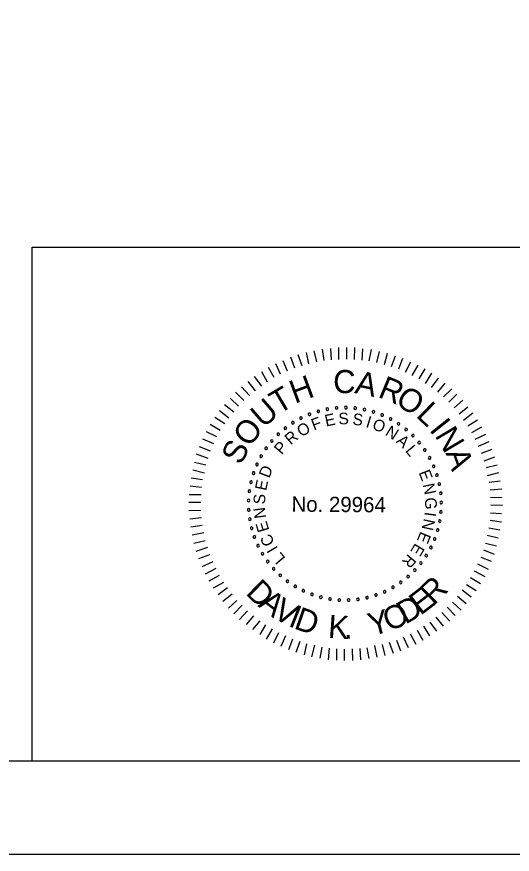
# Model space of a CAD drawing. Extents: x -144.4 to -96.3, y -117.1 to -87.8.
# Drawn here: x -114.36 to -110.83, y -117.06 to -111.1 of the extents above; entities that cross this region are included whole.
import ezdxf

# ---------------------------------------------------------------- set-up
doc = ezdxf.new("R2010")
doc.units = 0
for name, color, linetype in [('BR_BORDER LINES', 7, 'Continuous'), ('BR_TEXT', 7, 'Continuous'), ('Level 31', 7, 'Continuous')]:
    doc.layers.add(name, color=color, linetype=linetype)

msp = doc.modelspace()

# ---------------------------------------------------------------- linework, layer by layer
at = {"layer": 'BR_BORDER LINES'}
for p, q in [((-114.2473, -112.7399), (-107.1116, -112.7399)), ((-114.2473, -116.3975), (-114.2473, -112.7399)), ((-141.9121, -116.3976), (-97.1362, -116.3976))]:
    msp.add_line(p, q, dxfattribs=at)
at = {"layer": 'BR_TEXT'}
for p, q in [((-112.2228, -113.557), (-112.2416, -113.4781)), ((-112.1703, -113.5472), (-112.1822, -113.4661)), ((-112.1177, -113.5419), (-112.1228, -113.4608)), ((-112.0652, -113.5389), (-112.0645, -113.4533)), ((-112.0093, -113.536), (-112.0086, -113.4538)), ((-111.9533, -113.5398), (-111.9504, -113.4542)), ((-111.8998, -113.5437), (-111.8934, -113.4627)), ((-111.8484, -113.5498), (-111.834, -113.4689)), ((-111.7949, -113.5606), (-111.776, -113.4819)), ((-112.3785, -113.6003), (-112.4063, -113.5224)), ((-112.3258, -113.5835), (-112.3549, -113.5069)), ((-112.2778, -113.5703), (-112.2953, -113.4891)), ((-111.7402, -113.5747), (-111.719, -113.4939)), ((-111.6913, -113.5888), (-111.6621, -113.5126)), ((-111.6389, -113.6064), (-111.6097, -113.529)), ((-112.5251, -113.6687), (-112.5656, -113.5964)), ((-112.4793, -113.6451), (-112.5141, -113.5706)), ((-112.43, -113.6227), (-112.4613, -113.5482)), ((-111.5911, -113.6296), (-111.554, -113.5557)), ((-111.5434, -113.6528), (-111.5017, -113.579)), ((-111.4934, -113.6772), (-111.4505, -113.6056)), ((-112.6135, -113.7284), (-112.6654, -113.6607)), ((-112.5722, -113.7002), (-112.6126, -113.628)), ((-111.4491, -113.7095), (-111.404, -113.6379)), ((-112.6583, -113.7623), (-112.7114, -113.6956)), ((-111.4048, -113.7384), (-111.3563, -113.6715)), ((-111.3618, -113.773), (-111.3076, -113.7072)), ((-112.741, -113.8312), (-112.7999, -113.7725)), ((-112.702, -113.795), (-112.7574, -113.7352)), ((-111.3198, -113.8064), (-111.2623, -113.7476)), ((-111.2825, -113.8433), (-111.2249, -113.7855)), ((-112.7802, -113.872), (-112.838, -113.8156)), ((-111.2451, -113.8847), (-111.1819, -113.8293)), ((-112.8482, -113.9582), (-112.914, -113.9051)), ((-112.8136, -113.914), (-112.8794, -113.862)), ((-111.209, -113.9272), (-111.1469, -113.8764)), ((-112.8771, -113.9967), (-112.9486, -113.9528)), ((-111.1773, -113.972), (-111.1119, -113.92)), ((-112.9095, -114.0456), (-112.981, -114.0028)), ((-111.148, -114.011), (-111.0781, -113.9682)), ((-111.1187, -114.0604), (-111.0476, -114.0187)), ((-112.9327, -114.091), (-113.0077, -114.0539)), ((-111.0952, -114.1062), (-111.0184, -114.0703)), ((-112.9559, -114.1399), (-113.0321, -114.1062)), ((-111.0716, -114.1555), (-110.996, -114.123)), ((-112.9792, -114.1911), (-113.0565, -114.1619)), ((-111.0492, -114.2071), (-110.9736, -114.1791)), ((-112.9956, -114.2446), (-113.0775, -114.2143)), ((-111.0314, -114.2608), (-110.9546, -114.2318)), ((-113.0119, -114.2924), (-113.0928, -114.2723)), ((-111.018, -114.3089), (-110.938, -114.2901)), ((-113.0215, -114.3483), (-113.1047, -114.327)), ((-111.0071, -114.3649), (-110.927, -114.345)), ((-113.0418, -114.4508), (-113.1239, -114.441)), ((-113.0356, -114.3961), (-113.1166, -114.3851)), ((-110.9961, -114.4129), (-110.9173, -114.4033)), ((-110.9874, -114.4678), (-110.9063, -114.4593)), ((-113.0484, -114.558), (-113.1317, -114.5573)), ((-113.0456, -114.5033), (-113.1312, -114.5026)), ((-110.9856, -114.5203), (-110.9057, -114.521)), ((-113.0466, -114.6151), (-113.1322, -114.6167)), ((-110.9826, -114.5751), (-110.9016, -114.5757)), ((-113.0436, -114.6665), (-113.1258, -114.6761)), ((-110.9865, -114.6321), (-110.9066, -114.6351)), ((-113.0383, -114.7213), (-113.1195, -114.7332)), ((-110.9988, -114.7382), (-110.9201, -114.7514)), ((-110.9892, -114.6835), (-110.9082, -114.6944)), ((-113.0251, -114.774), (-113.1085, -114.7915)), ((-111.0106, -114.7906), (-110.9309, -114.8095)), ((-113.0164, -114.83), (-113.0976, -114.8487)), ((-111.0225, -114.8464), (-110.9428, -114.8665)), ((-113.0008, -114.8791), (-113.0832, -114.907)), ((-111.0366, -114.8954), (-110.9604, -114.9245)), ((-112.9853, -114.9306), (-113.0631, -114.9585)), ((-111.0553, -114.9466), (-110.9802, -114.9757)), ((-112.9628, -114.9799), (-113.0396, -115.0158)), ((-112.9404, -115.028), (-113.016, -115.0674)), ((-111.0785, -114.9955), (-111.0035, -115.0326)), ((-112.918, -115.0773), (-112.9902, -115.1189)), ((-111.1273, -115.0921), (-111.0568, -115.1349)), ((-111.1029, -115.0432), (-111.0267, -115.0838)), ((-112.8864, -115.1267), (-112.9587, -115.1683)), ((-111.1574, -115.1409), (-111.0881, -115.1837)), ((-112.8582, -115.1657), (-112.9248, -115.2142)), ((-112.8244, -115.2105), (-112.891, -115.2624)), ((-111.1873, -115.1795), (-111.1227, -115.2291)), ((-112.7916, -115.2553), (-112.8503, -115.3096)), ((-111.2565, -115.2679), (-111.1942, -115.3233)), ((-111.2197, -115.2237), (-111.1585, -115.2768)), ((-112.7531, -115.2898), (-112.8129, -115.3498)), ((-112.7146, -115.3301), (-112.771, -115.3913)), ((-111.2945, -115.3019), (-111.2379, -115.3628)), ((-112.6715, -115.3647), (-112.7257, -115.427)), ((-111.375, -115.3754), (-111.3219, -115.4386)), ((-111.3325, -115.3415), (-111.276, -115.4036)), ((-112.6273, -115.3993), (-112.6803, -115.4628)), ((-112.5864, -115.4282), (-112.6281, -115.4974)), ((-111.4634, -115.4375), (-111.4194, -115.5074)), ((-111.4186, -115.4093), (-111.3712, -115.4736)), ((-112.5399, -115.4582), (-112.5816, -115.5298)), ((-112.4944, -115.4848), (-112.5305, -115.5588)), ((-112.4456, -115.5081), (-112.4781, -115.582)), ((-111.6067, -115.515), (-111.5708, -115.5895)), ((-111.5586, -115.4926), (-111.5181, -115.5671)), ((-111.5081, -115.4667), (-111.4665, -115.539)), ((-112.3944, -115.5313), (-112.4235, -115.6064)), ((-112.342, -115.5477), (-112.3724, -115.6251)), ((-112.2942, -115.5641), (-112.3131, -115.6427)), ((-112.2395, -115.5737), (-112.2596, -115.6557)), ((-111.7567, -115.5686), (-111.7368, -115.6475)), ((-111.7075, -115.553), (-111.6796, -115.6308)), ((-111.6548, -115.5374), (-111.6269, -115.613)), ((-112.1872, -115.589), (-112.2003, -115.6665)), ((-112.1347, -115.5951), (-112.1411, -115.6773)), ((-112.0822, -115.599), (-112.0829, -115.6812)), ((-112.0263, -115.6029), (-112.027, -115.6839)), ((-111.9704, -115.5999), (-111.9688, -115.6821)), ((-111.9167, -115.5969), (-111.9117, -115.6791)), ((-111.8653, -115.5917), (-111.8522, -115.6693)), ((-111.8115, -115.5772), (-111.794, -115.6596))]:
    msp.add_line(p, q, dxfattribs=at)
for centre, start, end in [((-112.2114, -113.9083), 16.14222, 196.14222), ((-112.1469, -113.8931), 10.60376, 190.60376), ((-112.1469, -113.8931), 190.60376, 10.60376), ((-112.0812, -113.8842), 5.06529, 185.06529), ((-112.0812, -113.8842), 185.06529, 5.06529), ((-112.015, -113.8817), 359.52683, 179.52683), ((-112.015, -113.8817), 179.52683, 359.52683), ((-111.9488, -113.8855), 353.98837, 173.98837), ((-111.9488, -113.8855), 173.98837, 353.98837), ((-111.8833, -113.8958), 168.44991, 348.44991), ((-111.8833, -113.8958), 348.44991, 168.44991), ((-111.8191, -113.9123), 342.91145, 162.91145), ((-112.3345, -113.957), 27.21914, 207.21914), ((-112.3345, -113.957), 207.21914, 27.21914), ((-112.2741, -113.9297), 21.68068, 201.68068), ((-112.2741, -113.9297), 201.68068, 21.68068), ((-112.2114, -113.9083), 196.14222, 16.14222), ((-111.8191, -113.9123), 162.91145, 342.91145), ((-111.7569, -113.9349), 157.37299, 337.37299), ((-111.7569, -113.9349), 337.37299, 157.37299), ((-111.697, -113.9635), 151.83453, 331.83453), ((-111.697, -113.9635), 331.83453, 151.83453), ((-112.446, -114.0284), 38.29606, 218.29606), ((-112.446, -114.0284), 218.29606, 38.29606), ((-112.392, -113.99), 32.7576, 212.7576), ((-112.392, -113.99), 212.7576, 32.7576), ((-111.6403, -113.9977), 146.29606, 326.29606), ((-111.6403, -113.9977), 326.29606, 146.29606), ((-112.496, -114.0718), 43.83453, 223.83453), ((-112.496, -114.0718), 223.83453, 43.83453), ((-111.587, -114.0372), 140.7576, 320.7576), ((-111.587, -114.0372), 320.7576, 140.7576), ((-111.5379, -114.0816), 135.21914, 315.21914), ((-111.5379, -114.0816), 315.21914, 135.21914), ((-112.5417, -114.1199), 49.37299, 229.37299), ((-112.5417, -114.1199), 229.37299, 49.37299), ((-111.4933, -114.1306), 129.68068, 309.68068), ((-111.4933, -114.1306), 309.68068, 129.68068), ((-112.5824, -114.1721), 54.91145, 234.91145), ((-112.5824, -114.1721), 234.91145, 54.91145), ((-111.4536, -114.1837), 124.14222, 304.14222), ((-111.4536, -114.1837), 304.14222, 124.14222), ((-112.618, -114.2281), 60.44991, 240.44991), ((-112.618, -114.2281), 240.44991, 60.44991), ((-111.4192, -114.2403), 118.60376, 298.60376), ((-111.4192, -114.2403), 298.60376, 118.60376), ((-112.648, -114.2872), 65.98837, 245.98837), ((-112.648, -114.2872), 245.98837, 65.98837), ((-111.3904, -114.3001), 113.06529, 293.06529), ((-111.3904, -114.3001), 293.06529, 113.06529), ((-112.6721, -114.3489), 71.52683, 251.52683), ((-112.6721, -114.3489), 251.52683, 71.52683), ((-111.3675, -114.3623), 107.52683, 287.52683), ((-111.3675, -114.3623), 287.52683, 107.52683), ((-112.6902, -114.4127), 77.06529, 257.06529), ((-112.6902, -114.4127), 257.06529, 77.06529), ((-111.3508, -114.4264), 101.98837, 281.98837), ((-111.3508, -114.4264), 281.98837, 101.98837), ((-112.702, -114.4779), 82.60376, 262.60376), ((-112.702, -114.4779), 262.60376, 82.60376), ((-111.3403, -114.4918), 96.44991, 276.44991), ((-111.3403, -114.4918), 276.44991, 96.44991), ((-112.7075, -114.5439), 88.14222, 268.14222), ((-112.7075, -114.5439), 268.14222, 88.14222), ((-111.3362, -114.558), 90.91145, 270.91145), ((-111.3362, -114.558), 270.91145, 90.91145), ((-112.7065, -114.6102), 93.68068, 273.68068), ((-112.7065, -114.6102), 273.68068, 93.68068), ((-111.3385, -114.6242), 85.37299, 265.37299), ((-111.3385, -114.6242), 265.37299, 85.37299), ((-112.6992, -114.6761), 99.21914, 279.21914), ((-112.6992, -114.6761), 279.21914, 99.21914), ((-111.3471, -114.6899), 79.83453, 259.83453), ((-111.3471, -114.6899), 259.83453, 79.83453), ((-112.6856, -114.7409), 104.7576, 284.7576), ((-112.6856, -114.7409), 284.7576, 104.7576), ((-112.6658, -114.8042), 110.29606, 290.29606), ((-112.6658, -114.8042), 290.29606, 110.29606), ((-111.3621, -114.7545), 74.29606, 254.29606), ((-111.3621, -114.7545), 254.29606, 74.29606), ((-112.6399, -114.8652), 115.83453, 295.83453), ((-112.6399, -114.8652), 295.83453, 115.83453), ((-111.3832, -114.8173), 68.7576, 248.7576), ((-111.3832, -114.8173), 248.7576, 68.7576), ((-112.6083, -114.9234), 121.37299, 301.37299), ((-112.6083, -114.9234), 301.37299, 121.37299), ((-111.4103, -114.8778), 63.21914, 243.21914), ((-111.4103, -114.8778), 243.21914, 63.21914), ((-112.5712, -114.9784), 126.91145, 306.91145), ((-112.5712, -114.9784), 306.91145, 126.91145), ((-111.4431, -114.9354), 57.68068, 237.68068), ((-111.4431, -114.9354), 237.68068, 57.68068), ((-112.529, -115.0294), 132.44991, 312.44991), ((-112.529, -115.0294), 312.44991, 132.44991), ((-111.5246, -115.0397), 46.60376, 226.60376), ((-111.5246, -115.0397), 226.60376, 46.60376), ((-111.4813, -114.9895), 52.14222, 232.14222), ((-111.4813, -114.9895), 232.14222, 52.14222), ((-112.4821, -115.0762), 137.98837, 317.98837), ((-112.4821, -115.0762), 317.98837, 137.98837), ((-111.5724, -115.0855), 41.06529, 221.06529), ((-111.5724, -115.0855), 221.06529, 41.06529), ((-112.4308, -115.1182), 143.52683, 323.52683), ((-112.4308, -115.1182), 323.52683, 143.52683), ((-112.3757, -115.1551), 149.06529, 329.06529), ((-112.3757, -115.1551), 329.06529, 149.06529), ((-111.6803, -115.1623), 29.98837, 209.98837), ((-111.6803, -115.1623), 209.98837, 29.98837), ((-111.6245, -115.1265), 35.52683, 215.52683), ((-111.6245, -115.1265), 215.52683, 35.52683), ((-112.3174, -115.1865), 154.60376, 334.60376), ((-112.3174, -115.1865), 334.60376, 154.60376), ((-112.2563, -115.2122), 160.14222, 340.14222), ((-112.2563, -115.2122), 340.14222, 160.14222), ((-111.801, -115.2168), 18.91145, 198.91145), ((-111.801, -115.2168), 198.91145, 18.91145), ((-111.7393, -115.1925), 24.44991, 204.44991), ((-111.7393, -115.1925), 204.44991, 24.44991), ((-112.1929, -115.2318), 165.68068, 345.68068), ((-112.1929, -115.2318), 345.68068, 165.68068), ((-112.128, -115.2452), 171.21914, 351.21914), ((-112.128, -115.2452), 351.21914, 171.21914), ((-112.0621, -115.2522), 356.7576, 176.7576), ((-112.0621, -115.2522), 176.7576, 356.7576), ((-111.9959, -115.2529), 2.29606, 182.29606), ((-111.9959, -115.2529), 182.29606, 2.29606), ((-111.9298, -115.2472), 7.83453, 187.83453), ((-111.9298, -115.2472), 187.83453, 7.83453), ((-111.8647, -115.2351), 13.37299, 193.37299), ((-111.8647, -115.2351), 193.37299, 13.37299)]:
    msp.add_arc(centre, 0.00932, start, end, dxfattribs=at)
at = {"layer": 'Level 31'}
msp.add_lwpolyline([(-144.3504, -117.0625), (-96.4704, -117.0625), (-96.4704, -87.8025), (-144.3504, -87.8025)], close=True, dxfattribs=at)

# ---------------------------------------------------------------- texts
at = {"layer": 'BR_TEXT'}
for s, height, rotation, p in [('H', 0.165, 20.36371, (-112.3779, -113.856)), ('C', 0.165, 359.54822, (-112.106, -113.7785)), ('A', 0.165, 348.19813, (-111.9578, -113.7774)), ('R', 0.165, 337.43439, (-111.7939, -113.8038)), ('T', 0.165, 30.49921, (-112.4948, -113.9326)), ('O', 0.1648, 326.58689, (-111.6712, -113.8527)), ('U', 0.165, 40.80225, (-112.6028, -114.032)), ('L', 0.165, 315.94879, (-111.5215, -113.9429)), ('F', 0.0828, 20.61271, (-112.2432, -114.0461)), ('E', 0.0828, 11.41035, (-112.1565, -114.0172)), ('S', 0.0828, 2.20798, (-112.0664, -114.0026)), ('S', 0.0828, 352.66081, (-111.9716, -114.0029)), ('I', 0.0828, 343.11363, (-111.8782, -114.0189)), ('O', 0.0828, 338.43918, (-111.8337, -114.0323)), ('I', 0.165, 308.66128, (-111.4266, -114.0417)), ('O', 0.165, 52.0267, (-112.7019, -114.1702)), ('O', 0.0828, 30.84774, (-112.3328, -114.094)), ('N', 0.0828, 328.20415, (-111.7411, -114.0741)), ('N', 0.165, 300.70365, (-111.3859, -114.0808)), ('R', 0.0828, 40.39491, (-112.4075, -114.1523)), ('S', 0.1648, 63.25114, (-112.7623, -114.2973)), ('P', 0.0828, 49.94209, (-112.4715, -114.2223)), ('A', 0.0828, 318.65698, (-111.6627, -114.1274)), ('L', 0.0828, 309.45461, (-111.5965, -114.1903)), ('A', 0.165, 289.47921, (-111.3072, -114.2045)), ('D', 0.0828, 69.03644, (-112.5605, -114.3889)), ('E', 0.0828, 291.049, (-111.4982, -114.3437)), ('E', 0.0828, 78.23881, (-112.5825, -114.4776)), ('N', 0.0828, 281.84664, (-111.4687, -114.4301)), ('S', 0.0828, 87.78598, (-112.5901, -114.5721)), ('No. 29964', 0.10872, 359.52683, (-112.4024, -114.6231)), ('G', 0.0828, 272.29946, (-111.4531, -114.5236)), ('N', 0.0828, 97.33316, (-112.5819, -114.6665)), ('N', 0.0828, 257.73391, (-111.4596, -114.6679)), ('I', 0.0828, 262.40836, (-111.4535, -114.6218)), ('E', 0.0828, 106.53552, (-112.5593, -114.755)), ('C', 0.0828, 116.42662, (-112.5196, -114.8448)), ('E', 0.0828, 248.18673, (-111.4836, -114.7596)), ('E', 0.0828, 238.98437, (-111.5208, -114.843)), ('I', 0.0828, 121.10107, (-112.4956, -114.8845)), ('L', 0.0828, 129.95951, (-112.4415, -114.9539)), ('R', 0.0828, 229.78201, (-111.5708, -114.9195)), ('R', 0.1643, 44.59474, (-111.3903, -115.2946)), ('D', 0.1643, 315.40526, (-112.7347, -115.2074)), ('E', 0.1643, 37.53391, (-111.4842, -115.3663)), ('A', 0.1643, 322.83772, (-112.6461, -115.2947)), ('V', 0.1643, 330.51792, (-112.5435, -115.3721)), ('D', 0.1643, 30.10145, (-111.5918, -115.4287)), ('I', 0.1643, 338.19813, (-112.4315, -115.4351)), ('D', 0.1643, 340.79949, (-112.3918, -115.453)), ('Y', 0.1643, 14.86491, (-111.8327, -115.5106)), ('O', 0.1643, 22.42125, (-111.7105, -115.478)), ('K', 0.1643, 356.09796, (-112.1454, -115.5202)), ('.', 0.1643, 3.15879, (-112.0275, -115.5287))]:
    msp.add_text(s, height=height, rotation=rotation, dxfattribs=at).set_placement(p)

doc.saveas('drawing.dxf')
